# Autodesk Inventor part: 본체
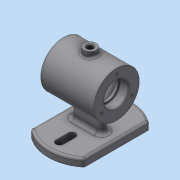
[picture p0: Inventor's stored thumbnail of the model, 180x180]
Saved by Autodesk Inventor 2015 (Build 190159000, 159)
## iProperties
Created: 2017-12
Part Number: 본체
Material: 일반
Document SubType Name: Modeling
Designer: SCD-A011
Density: 1 g/cm^3
Appearance: 기본값
Author: SCD-A011
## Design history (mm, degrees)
sketch "스케치3"
  geometry: L1 (35, 42.426)-(35, -42.426); L2 (-35, -42.426)-(-35, 42.426); A1 r 55 centre (0, 0) between (-35, -42.426) and (35, -42.426); A2 r 55 centre (0, 0) between (35, 42.426) and (-35, 42.426); 3 further points
  constraints: 4 end point, 4 point on circle, 2 centre point, 1 coincident, 1 horizontal alignment, 1 midpoint, 1 parallel, 1 vertical alignment
extrude "돌출2" new body sketch "스케치3" distance "d8" = 10; taper "d9" = 0 deg
sketch "스케치4"
  geometry: L1 (15, 0)-(-15, 0); L2 (15, 5)-(-15, 5); L3 (-15, -5)-(15, -5); A1 r 55 centre (0, 0) between (-35, -42.426) and (35, -42.426) reference; A2 r 5 centre (15, 0) between (15, -5) and (15, 5); A3 r 5 centre (-15, 0) between (-15, 5) and (-15, -5); 1 further point
  constraints: 8 end point, 4 point on circle, 4 tangent, 2 centre point, 1 coincident, 1 horizontal, 1 midpoint, 1 parallel
  dimensions: "d10" = 30 distance of L1.start L1.end; "d74" = 5 radius of A2
extrude "돌출3" join sketch "스케치4" distance "d11" = 52; taper "d12" = 0 deg
sketch "스케치5"
  geometry: L1 (-55, 0)-(-55, 10) reference; L2 (-55, 10)-(-5, 10) reference; L3 (-5, 10)-(-5, 62) reference; L4 (-5, 62)-(5, 62) reference; L5 (5, 62)-(5, 10) reference; L6 (5, 10)-(55, 10) reference; L7 (55, 10)-(55, 0) reference; L8 (55, 0)-(-55, 0) reference; C1 r 30 at (0, 62); 2 further points
  constraints: 1 centre point, 1 coincident, 1 midpoint
  dimensions: "d13" = 60 diameter of C1
extrude "돌출4" join sketch "스케치5" stored distance "d14" = 70; taper "d15" = 0 deg
sketch "스케치6"
  geometry: C1 r 30 at (0, 0) reference; C2 r 16 at (0, 0); 1 further point
  constraints: 1 centre point, 1 coincident
  dimensions: "d16" = 32 diameter of C2
extrude "돌출5" cut sketch "스케치6" distance "d17" = 12; taper "d18" = 0 deg
sketch "스케치7"
  geometry: C1 r 16 at (0, 0) reference; C2 r 14 at (0, 0); 1 further point
  constraints: 1 centre point, 1 coincident
  dimensions: "d19" = 28 diameter of C2
extrude "돌출6" cut sketch "스케치7" distance "d20" = 3; taper "d21" = 0 deg
sketch "스케치8"
  geometry: C1 r 14 at (0, 0) reference; C2 r 25 at (0, 0); 1 further point
  constraints: 1 centre point, 1 coincident
  dimensions: "d24" = 50 diameter of C2
extrude "돌출7" cut sketch "스케치8" distance "d22" = 40; taper "d23" = 0 deg
sketch "스케치9"
  geometry: C1 r 16 at (0, 0) reference; 2 further points
  constraints: 1 horizontal alignment
  dimensions: "d27" = 23 distance of C1.centre point (-23, 0)
hole "구멍1" sketch "스케치9" at (-23, 0) diameter "d28" = 3.242; stored, may be unused: countersink angle "d32" = 90 deg, drill point angle "d34" = 118 deg; dims "d29" = 8, "d30" = 4, "d31" = 2, "d33" = 10
node "작업 평면1"
sketch "스케치10"
  geometry: C1 r 8 at (0, 0); 1 further point
  constraints: 1 centre point, 1 coincident
  dimensions: "d39" = 16 diameter of C1
extrude "돌출8" join sketch "스케치10" stored distance "d40" = 40; taper "d41" = 0 deg
sketch "스케치11"
  geometry: C1 r 8 at (0, 0) reference; C2 r 4 at (0, 0)
  constraints: 1 centre point, 1 coincident
  dimensions: "d42" = 8 diameter of C2
extrude "돌출9" cut sketch "스케치11" stored distance "d43" = 40; taper "d44" = 0 deg
fillet "모깎기1" dims "d45" = 3
fillet "모깎기2" dims "d46" = 3
fillet "모깎기3" dims "d47" = 3
fillet "모깎기4" dims "d48" = 5
fillet "모깎기5" dims "d49" = 5
chamfer "모따기1" distance "d50" = 1; stored, may be unused: second distance "d51" = 2, angle "d52" = 45 deg
chamfer "모따기2" distance "d53" = 1; stored, may be unused: second distance "d54" = 2, angle "d55" = 45 deg
fillet "모깎기6" dims "d56" = 0.3
fillet "모깎기7" dims "d57" = 3
sketch "스케치12"
  geometry: L1 (0, -24)-(0, -40); L2 (5, -24)-(5, -40); L3 (-5, -40)-(-5, -24); A1 r 52 centre (0, 0) between (32, 40.988) and (-32, 40.988) reference; A2 r 10 centre (15, 0) between (15, -10) and (15, 10) reference; A3 r 5 centre (0, -24) between (5, -24) and (-5, -24); A4 r 5 centre (0, -40) between (-5, -40) and (5, -40); A5 r 5 centre (0, -40) between (-5, -40) and (5, -40); A6 r 5 centre (0, -24) between (5, -24) and (-5, -24); 1 further point
  constraints: 8 end point, 8 point on circle, 4 centre point, 4 tangent, 2 coincident, 2 concentric, 1 midpoint, 1 parallel, 1 vertical, 1 vertical alignment
  dimensions: "d60" = 16 distance of L2.end L2.start; "d61" = 24 vertical distance of L2.start A2.centre; "d62" = 5 radius of A3
extrude "돌출10" cut sketch "스케치12" stored distance "d63" = 40; taper "d64" = 0 deg
node "작업 평면6"
sketch "스케치18"
  geometry: L1 (33.846, 0)-(-33.846, 0) reference; 3 further points
  constraints: 1 midpoint, 1 vertical alignment, 1 other
  dimensions: "d71" = 62 distance from line of L1 point (0, 62)
feature "엠보싱1" sketch "스케치18" dims "d72" = 0.5, "d73" = 0
node "솔리드2"
mirror "대칭1"
pattern_circular "원형 패턴1" dims angle "d36" = 360 deg
mirror "대칭2"
mirror "대칭3"
node "절단 모서리 투영1"
other parameters: "d38" = 99
